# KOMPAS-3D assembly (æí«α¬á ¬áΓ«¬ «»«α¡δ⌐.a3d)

Referenced files in D:\МОДЕЛЬ ТАНКА Т90\ДЕТАЛИ\ХОДОВАЯ\Каток опорный с балансиром\: каток опорный2.m3d, втулка соеденения катков.m3d, шпилька соеденения катков.m3d
Referenced files in D:\МОДЕЛЬ ТАНКА Т90\ДЕТАЛИ\ОБЩИЕ ДЕТАЛИ\: подшипник 13-5-4.m3d
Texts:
  Сборка каток опорный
